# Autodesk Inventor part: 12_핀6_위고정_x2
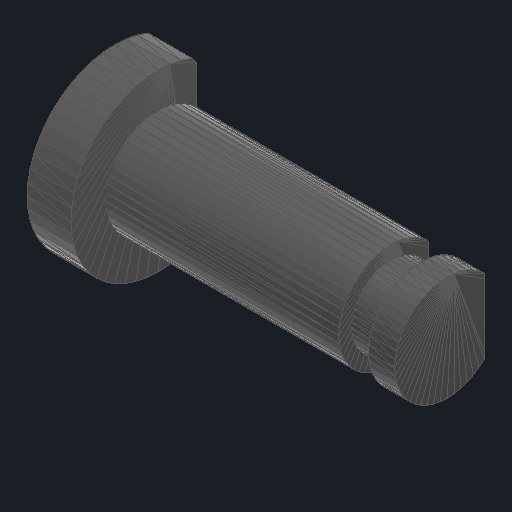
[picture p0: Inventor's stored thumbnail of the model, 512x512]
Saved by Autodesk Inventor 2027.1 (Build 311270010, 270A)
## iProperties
Created: 2026-11
Part Number: 12_핀6_위고정_x2
Material: 일반
Document SubType Name: Modeling
Designer: djshs
Density: 1 g/cm^3
Appearance: 기본값
Author: djshs
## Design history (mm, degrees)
node "12_핀6_위고정_x2"
  node "MeshFeature1"
